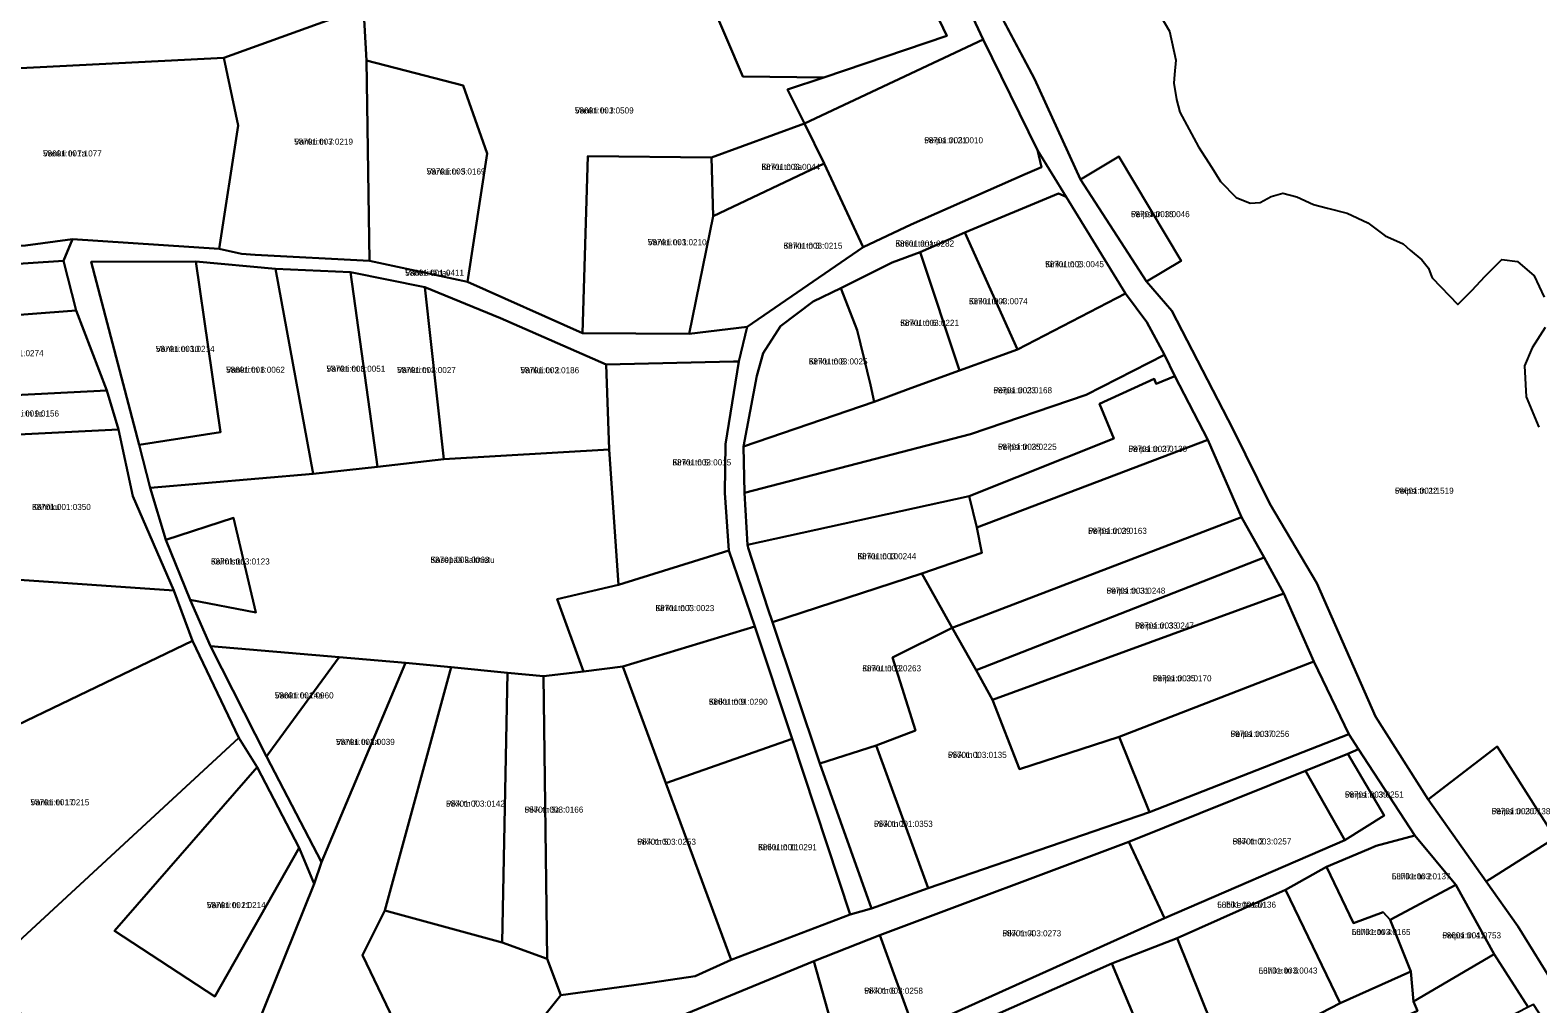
# Model space of a CAD drawing. Extents: x 663371 to 690098, y 6476568 to 6518353.
# Drawn here: x 687904.6 to 688276.7, y 6492280 to 6492520.5 of the extents above; entities that cross this region are included whole.
import ezdxf

# ---------------------------------------------------------------- set-up
doc = ezdxf.new("R2010")
doc.units = 0
for name, color, linetype in [('L_AADRESS', 7, 'Continuous'), ('PIIR', 7, 'Continuous'), ('TUNNUS', 7, 'Continuous')]:
    doc.layers.add(name, color=color, linetype=linetype)

msp = doc.modelspace()

# ---------------------------------------------------------------- linework, layer by layer
at = {"layer": 'PIIR'}
for points in [[(687919.02, 6492840.71), (687943.62, 6492789.47), (687948.89, 6492780.18), (687957.42, 6492767.74), (687964.9, 6492758.61), (687985.77, 6492739.07), (688015.25, 6492717.52), (688014.84, 6492716.95), (687998.32, 6492695.33), (688028.7, 6492662.54), (688033.9, 6492656.68), (687990.98, 6492641.02), (687973.52, 6492619.07), (687972.11, 6492556.04), (687977.61, 6492541.58), (687986.85, 6492526.07), (687952.4, 6492513.63), (687860.02, 6492508.91)], [(688278.99, 6492274.73), (688275.61, 6492279.88), (688274.32, 6492279.22), (688265.92, 6492292.28), (688256.41, 6492309.4), (688246.32, 6492321.62), (688232.41, 6492342.93), (688230, 6492346.63), (688221.38, 6492364.54), (688213.95, 6492381.34), (688209.13, 6492390.26), (688203.57, 6492400.22), (688195.24, 6492419.29), (688187.08, 6492435), (688184.54, 6492440.33), (688180.18, 6492448.35), (688174.88, 6492455.41), (688160.23, 6492479.29), (688153.21, 6492490.87), (688139.77, 6492518.16), (688125.34, 6492549.07)], [(688140.56, 6492530.91), (688152.43, 6492508.44), (688163.82, 6492483.59), (688180.1, 6492458.37), (688186.35, 6492451.18), (688201.49, 6492421.9), (688210.55, 6492403.48), (688222.14, 6492383.92), (688236.61, 6492351), (688249.61, 6492330.52), (688263.9, 6492310.29), (688271.73, 6492299.19), (688281.22, 6492283.96)], [(688281.22, 6492283.96), (688271.73, 6492299.19), (688263.9, 6492310.29), (688280.93, 6492321.06), (688266.61, 6492343.61), (688249.61, 6492330.52), (688236.61, 6492351), (688222.14, 6492383.92), (688210.55, 6492403.48), (688201.49, 6492421.9), (688186.35, 6492451.18), (688180.1, 6492458.37), (688188.68, 6492463.51), (688173.26, 6492489.24), (688163.82, 6492483.59), (688152.43, 6492508.44), (688140.62, 6492530.8)], [(688183.13, 6492524.64), (688185.79, 6492520.2), (688187.35, 6492513.05), (688187.01, 6492509.53), (688186.81, 6492507.39), (688187.51, 6492503.36), (688188.33, 6492500.18), (688192.91, 6492491.64), (688196.18, 6492486.56), (688198.32, 6492483.07), (688202.22, 6492479.12), (688205.64, 6492477.75), (688208.12, 6492477.95), (688210.85, 6492479.41), (688213.78, 6492480.23), (688217.19, 6492479.29), (688221.27, 6492477.4), (688224.73, 6492476.49), (688229.58, 6492475.25), (688234.74, 6492472.85), (688238.98, 6492469.67), (688242.52, 6492468.08), (688243.4, 6492467.69), (688245.2, 6492466.14), (688248.03, 6492463.72), (688249.69, 6492461.73), (688250.24, 6492460.17), (688250.56, 6492459.27), (688256.94, 6492452.76), (688260.49, 6492456.29), (688263.61, 6492459.64), (688267.25, 6492463.26), (688267.81, 6492463.82), (688271.63, 6492463.35), (688275.77, 6492459.84), (688278.2, 6492454.54)], [(688278.45, 6492447.06), (688275.31, 6492442.03), (688273.36, 6492437.6), (688273.79, 6492429.94), (688276.91, 6492422.4)], [(688007.94, 6492247.62), (688035.52, 6492282.19), (688055.96, 6492285.02), (688068.71, 6492286.9), (688077.56, 6492290.93), (688107, 6492302.08), (688112.22, 6492303.57), (688126.22, 6492308.65), (688180.84, 6492327.37), (688230, 6492346.63), (688232.41, 6492342.93), (688229.75, 6492341.79), (688219.35, 6492337.62), (688175.77, 6492320.04), (688114.31, 6492297.03), (688098.03, 6492290.61), (688061.06, 6492275.35)]]:
    msp.add_lwpolyline(points, dxfattribs=at)
for points in [[(687977.61, 6492541.58), (688034.88, 6492559.77), (688042.34, 6492548.11), (688047.6, 6492532.68), (688055.58, 6492534.27), (688060.58, 6492523.84), (688072.21, 6492528.37), (688080.45, 6492509), (688100.45, 6492508.81), (688091.5, 6492505.79), (688095.7, 6492497.39), (688072.78, 6492489.02), (688042.26, 6492489.34), (688040.92, 6492445.66), (688012.56, 6492458.29), (688017.36, 6492489.98), (688011.42, 6492506.84), (687987.57, 6492513.01), (687986.85, 6492526.07)], [(688139.77, 6492518.16), (688095.7, 6492497.39), (688091.5, 6492505.79), (688100.45, 6492508.81), (688130.83, 6492519.07), (688117.88, 6492546.17), (688125.34, 6492549.07)], [(688130.83, 6492519.07), (688100.45, 6492508.81), (688080.45, 6492509), (688072.21, 6492528.37), (688117.88, 6492546.17)], [(687955.96, 6492496.94), (687952.4, 6492513.63), (687986.85, 6492526.07), (687987.57, 6492513.01), (687988.32, 6492463.54), (687960.12, 6492464.96), (687956.75, 6492465.23), (687951.2, 6492466.48)], [(688139.77, 6492518.16), (688153.21, 6492490.87), (688154.16, 6492486.67), (688150.16, 6492484.89), (688122.03, 6492472.51), (688110.19, 6492466.92), (688100.56, 6492487.52), (688095.7, 6492497.39)], [(687955.96, 6492496.94), (687951.2, 6492466.48), (687915.08, 6492468.87), (687903.44, 6492467.31), (687869.52, 6492465.35), (687862.95, 6492464.93), (687861.03, 6492481.76), (687860.02, 6492508.91), (687952.4, 6492513.63)], [(687988.32, 6492463.54), (687987.57, 6492513.01), (688011.42, 6492506.84), (688017.36, 6492489.98), (688012.56, 6492458.29)], [(688100.56, 6492487.52), (688073.14, 6492474.53), (688072.78, 6492489.02), (688095.7, 6492497.39)], [(688040.92, 6492445.66), (688042.26, 6492489.34), (688072.78, 6492489.02), (688073.14, 6492474.53), (688067.23, 6492445.47)], [(688154.16, 6492486.67), (688153.21, 6492490.87), (688160.23, 6492479.29), (688158.39, 6492480.11), (688135.29, 6492470.54), (688124.28, 6492465.64), (688117.34, 6492463.1), (688104.69, 6492456.74), (688097.86, 6492453.45), (688089.77, 6492447.36), (688085.47, 6492440.7), (688083.9, 6492435.09), (688080.66, 6492417.7), (688080.89, 6492406.21), (688081.65, 6492393.37), (688081.76, 6492392.61), (688086.62, 6492377.63), (688087.76, 6492374.28), (688099.47, 6492339.4), (688112.22, 6492303.57), (688107, 6492302.08), (688092.61, 6492345.45), (688083.4, 6492373.2), (688077.02, 6492391.96), (688076.02, 6492406.19), (688076.23, 6492418.21), (688079.5, 6492438.68), (688081.51, 6492447.21), (688110.19, 6492466.92), (688122.03, 6492472.51), (688150.16, 6492484.89)], [(688073.14, 6492474.53), (688100.56, 6492487.52), (688110.19, 6492466.92), (688081.51, 6492447.21), (688067.23, 6492445.47)], [(688163.82, 6492483.59), (688173.26, 6492489.24), (688188.68, 6492463.51), (688180.1, 6492458.37)], [(688135.29, 6492470.54), (688158.39, 6492480.11), (688160.23, 6492479.29), (688174.88, 6492455.41), (688148.28, 6492441.6)], [(687856.56, 6492464.52), (687862.95, 6492464.93), (687869.52, 6492465.35), (687903.44, 6492467.31), (687915.08, 6492468.87), (687912.79, 6492463.47), (687865.33, 6492460.36), (687865.24, 6492447.41), (687868.47, 6492428.71), (687859.94, 6492432.28)], [(687912.79, 6492463.47), (687915.08, 6492468.87), (687951.2, 6492466.48), (687956.75, 6492465.23), (687960.12, 6492464.96), (687988.32, 6492463.54), (688012.56, 6492458.29), (688040.92, 6492445.66), (688067.23, 6492445.47), (688081.51, 6492447.21), (688079.5, 6492438.68), (688078.17, 6492438.67), (688046.73, 6492437.95), (688020.67, 6492449.38), (688002.03, 6492457.02), (687983.62, 6492460.68), (687965.14, 6492461.55), (687945.49, 6492463.31), (687919.63, 6492463.27), (687931.46, 6492418.1), (687934.21, 6492407.47), (687938.1, 6492394.65), (687944.11, 6492379.82), (687949.06, 6492368.35), (687962.89, 6492341.09), (687976.52, 6492315.01), (687974.65, 6492309.67), (687971.02, 6492318.59), (687960.6, 6492338.49), (687956.1, 6492345.77), (687944.65, 6492369.68), (687940.06, 6492382.09), (687929.94, 6492405.44), (687926.39, 6492421.88), (687923.55, 6492431.48), (687915.95, 6492451.22)], [(688124.28, 6492465.64), (688135.29, 6492470.54), (688148.28, 6492441.6), (688142.55, 6492439.52), (688133.96, 6492436.41)], [(687915.95, 6492451.22), (687865.24, 6492447.41), (687865.33, 6492460.36), (687912.79, 6492463.47)], [(687931.46, 6492418.1), (687919.63, 6492463.27), (687945.49, 6492463.31), (687951.58, 6492421.24)], [(687934.21, 6492407.47), (687931.46, 6492418.1), (687951.58, 6492421.24), (687945.49, 6492463.31), (687965.14, 6492461.55), (687974.43, 6492410.9)], [(688133.96, 6492436.41), (688121.93, 6492432.03), (688112.87, 6492428.72), (688111.99, 6492432.92), (688108.69, 6492446.39), (688104.69, 6492456.74), (688117.34, 6492463.1), (688124.28, 6492465.64)], [(687983.62, 6492460.68), (687990.33, 6492412.65), (687974.43, 6492410.9), (687965.14, 6492461.55)], [(688002.03, 6492457.02), (688006.69, 6492414.5), (687990.33, 6492412.65), (687983.62, 6492460.68)], [(688020.67, 6492449.38), (688046.73, 6492437.95), (688047.45, 6492416.94), (688006.69, 6492414.5), (688002.03, 6492457.02)], [(688104.69, 6492456.74), (688108.69, 6492446.39), (688111.99, 6492432.92), (688112.87, 6492428.72), (688080.66, 6492417.7), (688083.9, 6492435.09), (688085.47, 6492440.7), (688089.77, 6492447.36), (688097.86, 6492453.45)], [(688180.18, 6492448.35), (688184.54, 6492440.33), (688165.22, 6492430.41), (688136.65, 6492420.71), (688080.89, 6492406.21), (688080.66, 6492417.7), (688112.87, 6492428.72), (688121.93, 6492432.03), (688133.96, 6492436.41), (688142.55, 6492439.52), (688148.28, 6492441.6), (688174.88, 6492455.41)], [(687923.55, 6492431.48), (687868.47, 6492428.71), (687865.24, 6492447.41), (687915.95, 6492451.22)], [(688078.17, 6492438.67), (688079.5, 6492438.68), (688076.23, 6492418.21), (688076.02, 6492406.19), (688077.02, 6492391.96), (688049.79, 6492383.53), (688047.45, 6492416.94), (688046.73, 6492437.95)], [(688165.22, 6492430.41), (688184.54, 6492440.33), (688187.08, 6492435), (688182.5, 6492433.14), (688181.95, 6492434.35), (688168.53, 6492428.22), (688172.02, 6492419.63), (688136.3, 6492405.37), (688081.65, 6492393.37), (688080.89, 6492406.21), (688136.65, 6492420.71)], [(688181.95, 6492434.35), (688182.5, 6492433.14), (688187.08, 6492435), (688195.24, 6492419.29), (688138.25, 6492397.68), (688136.3, 6492405.37), (688172.02, 6492419.63), (688168.53, 6492428.22)], [(687869.85, 6492418.65), (687868.47, 6492428.71), (687923.55, 6492431.48), (687926.39, 6492421.88), (687875.39, 6492419.35)], [(687875.39, 6492419.35), (687926.39, 6492421.88), (687929.94, 6492405.44), (687940.06, 6492382.09), (687881.67, 6492386.14)], [(688139.48, 6492391.42), (688138.25, 6492397.68), (688195.24, 6492419.29), (688203.57, 6492400.22), (688132.17, 6492372.91), (688124.63, 6492386.3)], [(687934.21, 6492407.47), (687974.43, 6492410.9), (687990.33, 6492412.65), (688006.69, 6492414.5), (688047.45, 6492416.94), (688049.79, 6492383.53), (688034.67, 6492379.95), (688041.14, 6492362.07), (688031.24, 6492360.93), (688022.37, 6492361.77), (688008.51, 6492363.22), (687997.26, 6492364.25), (687980.89, 6492365.62), (687949.06, 6492368.35), (687944.11, 6492379.82), (687960.31, 6492376.68), (687954.75, 6492400.02), (687938.1, 6492394.65)], [(688081.65, 6492393.37), (688136.3, 6492405.37), (688138.25, 6492397.68), (688139.48, 6492391.42), (688124.63, 6492386.3), (688087.76, 6492374.28), (688086.62, 6492377.63), (688081.76, 6492392.61)], [(687938.1, 6492394.65), (687954.75, 6492400.02), (687960.31, 6492376.68), (687944.11, 6492379.82)], [(688132.17, 6492372.91), (688203.57, 6492400.22), (688209.13, 6492390.26), (688138.09, 6492362.42)], [(687940.06, 6492382.09), (687944.65, 6492369.68), (687869.01, 6492333.31), (687835.93, 6492389.45), (687881.67, 6492386.14)], [(688083.4, 6492373.2), (688050.89, 6492363.36), (688041.14, 6492362.07), (688034.67, 6492379.95), (688049.79, 6492383.53), (688077.02, 6492391.96)], [(688213.95, 6492381.34), (688142.05, 6492355.15), (688138.09, 6492362.42), (688209.13, 6492390.26)], [(688117.41, 6492365.59), (688123.08, 6492347.57), (688113.35, 6492343.86), (688099.47, 6492339.4), (688087.76, 6492374.28), (688124.63, 6492386.3), (688132.17, 6492372.91)], [(688221.38, 6492364.54), (688173.36, 6492345.94), (688148.79, 6492338.01), (688142.05, 6492355.15), (688213.95, 6492381.34)], [(688050.89, 6492363.36), (688083.4, 6492373.2), (688092.61, 6492345.45), (688061.49, 6492334.57)], [(688180.84, 6492327.37), (688126.22, 6492308.65), (688113.35, 6492343.86), (688123.08, 6492347.57), (688117.41, 6492365.59), (688132.17, 6492372.91), (688138.09, 6492362.42), (688142.05, 6492355.15), (688148.79, 6492338.01), (688173.36, 6492345.94)], [(687956.1, 6492345.77), (687895.03, 6492289.39), (687894.43, 6492288.82), (687894.03, 6492288.45), (687869.01, 6492333.31), (687944.65, 6492369.68)], [(687964.44, 6492343.19), (687962.89, 6492341.09), (687949.06, 6492368.35), (687980.89, 6492365.62)], [(687992.09, 6492303.09), (687986.57, 6492292.04), (688007.94, 6492247.62), (688005.84, 6492240.83), (687994.89, 6492222.84), (687977.17, 6492230.46), (687947.92, 6492243.24), (687974.65, 6492309.67), (687976.52, 6492315.01), (687997.26, 6492364.25), (688008.51, 6492363.22)], [(687976.52, 6492315.01), (687962.89, 6492341.09), (687964.44, 6492343.19), (687980.89, 6492365.62), (687997.26, 6492364.25)], [(688022.37, 6492361.77), (688021.07, 6492295.16), (687992.09, 6492303.09), (688008.51, 6492363.22)], [(688035.52, 6492282.19), (688032.16, 6492291.13), (688031.24, 6492360.93), (688041.14, 6492362.07), (688050.89, 6492363.36), (688061.49, 6492334.57), (688077.56, 6492290.93), (688068.71, 6492286.9), (688055.96, 6492285.02)], [(688173.36, 6492345.94), (688221.38, 6492364.54), (688230, 6492346.63), (688180.84, 6492327.37)], [(688021.07, 6492295.16), (688022.37, 6492361.77), (688031.24, 6492360.93), (688032.16, 6492291.13)], [(687895.03, 6492289.39), (687956.1, 6492345.77), (687960.6, 6492338.49), (687925.4, 6492298.08), (687950.14, 6492281.83), (687971.02, 6492318.59), (687974.65, 6492309.67), (687947.92, 6492243.24), (687944.94, 6492231.13), (687929.9, 6492232.35)], [(688061.49, 6492334.57), (688092.61, 6492345.45), (688107, 6492302.08), (688077.56, 6492290.93)], [(688232.41, 6492342.93), (688246.32, 6492321.62), (688236.81, 6492319.07), (688234.88, 6492318.24), (688224.53, 6492313.9), (688214.37, 6492308.19), (688187.68, 6492296.27), (688171.57, 6492290.01), (688118.51, 6492266.59), (688106.24, 6492264.66), (688095.83, 6492265.14), (688104.18, 6492268.6), (688114.71, 6492270.25), (688122.81, 6492273.41), (688184.51, 6492301.17), (688229.05, 6492320.45), (688238.77, 6492326.55), (688229.75, 6492341.79)], [(688112.22, 6492303.57), (688099.47, 6492339.4), (688113.35, 6492343.86), (688126.22, 6492308.65)], [(688229.05, 6492320.45), (688219.35, 6492337.62), (688229.75, 6492341.79), (688238.77, 6492326.55)], [(688266.61, 6492343.61), (688280.93, 6492321.06), (688263.9, 6492310.29), (688249.61, 6492330.52)], [(687925.4, 6492298.08), (687960.6, 6492338.49), (687971.02, 6492318.59), (687950.14, 6492281.83)], [(688219.35, 6492337.62), (688229.05, 6492320.45), (688184.51, 6492301.17), (688175.77, 6492320.04)], [(688175.77, 6492320.04), (688184.51, 6492301.17), (688122.81, 6492273.41), (688114.31, 6492297.03)], [(688231.15, 6492299.97), (688224.53, 6492313.9), (688234.88, 6492318.24), (688236.81, 6492319.07), (688246.32, 6492321.62), (688256.41, 6492309.4), (688240.25, 6492300.83), (688238.5, 6492302.68)], [(688214.37, 6492308.19), (688224.53, 6492313.9), (688231.15, 6492299.97), (688238.5, 6492302.68), (688240.25, 6492300.83), (688245.33, 6492288.06), (688227.86, 6492280.21)], [(688214.37, 6492308.19), (688227.86, 6492280.21), (688206.26, 6492269.01), (688196.27, 6492274.77), (688187.68, 6492296.27)], [(688240.25, 6492300.83), (688256.41, 6492309.4), (688265.92, 6492292.28), (688246.02, 6492280.66), (688245.33, 6492288.06)], [(687992.09, 6492303.09), (688021.07, 6492295.16), (688032.16, 6492291.13), (688035.52, 6492282.19), (688007.94, 6492247.62), (687986.57, 6492292.04)], [(688187.68, 6492296.27), (688196.27, 6492274.77), (688143.64, 6492250.23), (688133.88, 6492244.78), (688119.71, 6492231.98), (688063.83, 6492138.79), (688058.89, 6492147.33), (688118.33, 6492244.23), (688128.13, 6492253.4), (688154, 6492268.51), (688156.82, 6492263.95), (688177.94, 6492274.72), (688171.57, 6492290.01)], [(688098.03, 6492290.61), (688114.31, 6492297.03), (688122.81, 6492273.41), (688114.71, 6492270.25), (688104.18, 6492268.6)], [(688246.02, 6492280.66), (688265.92, 6492292.28), (688274.32, 6492279.22), (688222.97, 6492252.76), (688212.78, 6492262.68), (688246.98, 6492278.34)], [(688044.56, 6492221.61), (688061.06, 6492275.35), (688098.03, 6492290.61), (688104.18, 6492268.6), (688095.83, 6492265.14), (688083.21, 6492245.53), (688090.28, 6492240.52), (688063.09, 6492193.66), (688046.74, 6492172.12), (688041.18, 6492183.91), (688050.22, 6492197.52)], [(688052.37, 6492160.73), (688073.22, 6492185.93), (688118.51, 6492266.59), (688171.57, 6492290.01), (688177.94, 6492274.72), (688156.82, 6492263.95), (688154, 6492268.51), (688128.13, 6492253.4), (688118.33, 6492244.23), (688058.89, 6492147.33)], [(688212.78, 6492262.68), (688206.26, 6492269.01), (688227.86, 6492280.21), (688245.33, 6492288.06), (688246.02, 6492280.66), (688246.98, 6492278.34)]]:
    msp.add_lwpolyline(points, close=True, dxfattribs=at)

# ---------------------------------------------------------------- texts
at = {"layer": 'L_AADRESS'}
for s, p in [('Vankri tn 3', (688039.03, 6492499.89)), ('Vankri tn 7', (687969.76, 6492492.19)), ('Peipsi tn 21', (688125.24, 6492492.54)), ('Vankri tn 7a', (687907.76, 6492489.28)), ('Vankri tn 5', (688002.46, 6492484.82)), ('Kiriku tn 3a', (688085.06, 6492485.96)), ('Peipsi tn 18', (688176.25, 6492474.29)), ('Vankri tn 1', (688057.03, 6492467.36)), ('Kiriku tn 3', (688090.54, 6492466.49)), ('Kiriku tänav', (688118.12, 6492467.03)), ('Kiriku tn 2', (688155.09, 6492461.94)), ('Vankri tänav', (687997.15, 6492459.81)), ('Kiriku tn 4', (688136.28, 6492452.79)), ('Kiriku tn 6', (688119.32, 6492447.45)), ('Vankri tn 10', (687935.61, 6492441.02)), ('Vankri tn 8', (687952.95, 6492435.86)), ('Vankri tn 6', (687977.73, 6492436.11)), ('Vankri tn 4', (687995.15, 6492435.79)), ('Vankri tn 2', (688025.58, 6492435.76)), ('Kiriku tn 8', (688096.76, 6492437.92)), ('Peipsi tn 23', (688142.29, 6492430.81)), ('Vankri tn 9c', (687897.21, 6492425.07)), ('Peipsi tn 25', (688143.43, 6492416.85)), ('Peipsi tn 27', (688175.62, 6492416.34)), ('Kiriku tn 5', (688063.11, 6492412.99)), ('Peipsi tn 22', (688241.4, 6492406.01)), ('Kähriku', (687905.06, 6492401.99)), ('Peipsi tn 29', (688165.68, 6492396.1)), ('Kalmistu', (687949.21, 6492388.53)), ('Kasepää kalmistu', (688003.4, 6492388.94)), ('Kiriku tn 10', (688108.76, 6492389.83)), ('Peipsi tn 31', (688170.24, 6492381.32)), ('Kiriku tn 7', (688058.92, 6492377.02)), ('Peipsi tn 33', (688177.29, 6492372.71)), ('Kiriku tn 12', (688109.96, 6492362.15)), ('Peipsi tn 35', (688181.65, 6492359.68)), ('Vankri tn 14a', (687964.98, 6492355.45)), ('Kiriku tn 9', (688072.09, 6492353.88)), ('Vankri tn 14', (687980.07, 6492343.98)), ('Peipsi tn 37', (688200.84, 6492345.96)), ('Pikk tn 1', (688131.09, 6492340.78)), ('Vankri tn 17', (687904.69, 6492329.07)), ('Pikk tn 7', (688007.23, 6492328.74)), ('Peipsi tn 39', (688229.06, 6492330.98)), ('Pikk tn 5a', (688026.61, 6492327.26)), ('Peipsi tn 20', (688265.27, 6492326.87)), ('Pikk tn 3', (688112.84, 6492323.75)), ('Pikk tn 5', (688054.4, 6492319.32)), ('Kiriku tn 11', (688084.25, 6492317.99)), ('Pikk tn 2', (688201.34, 6492319.4)), ('Lühike tn 2', (688240.63, 6492310.79)), ('Vankri tn 21', (687948.21, 6492303.68)), ('Lühike tänav', (688197.55, 6492303.79)), ('Pikk tn 4', (688144.53, 6492296.73)), ('Lühike tn 4', (688230.75, 6492297.05)), ('Peipsi tn 41', (688253.09, 6492296.21)), ('Lühike tn 6', (688207.77, 6492287.52)), ('Pikk tn 6', (688110.42, 6492282.54))]:
    msp.add_text(s, height=1.5, dxfattribs=at).set_placement(p)
at = {"layer": 'TUNNUS'}
for s, p in [('58601:001:0509', (688039.03, 6492499.89)), ('58701:003:0219', (687969.76, 6492492.19)), ('58701:003:0010', (688125.24, 6492492.54)), ('58601:001:1077', (687907.76, 6492489.28)), ('58701:003:0169', (688002.46, 6492484.82)), ('58701:003:0044', (688085.06, 6492485.96)), ('58701:003:0046', (688176.25, 6492474.29)), ('58701:003:0210', (688057.03, 6492467.36)), ('58701:003:0215', (688090.54, 6492466.49)), ('58601:001:0282', (688118.12, 6492467.03)), ('58701:003:0045', (688155.09, 6492461.94)), ('58601:001:0411', (687997.15, 6492459.81)), ('58701:003:0074', (688136.28, 6492452.79)), ('58701:003:0221', (688119.32, 6492447.45)), ('58701:001:0274', (687893.4, 6492439.96)), ('58701:003:0214', (687935.61, 6492441.02)), ('58601:001:0062', (687952.95, 6492435.86)), ('58701:003:0051', (687977.73, 6492436.11)), ('58701:003:0027', (687995.15, 6492435.79)), ('58701:003:0186', (688025.58, 6492435.76)), ('58701:003:0025', (688096.76, 6492437.92)), ('58701:003:0168', (688142.29, 6492430.81)), ('58701:001:0156', (687897.21, 6492425.07)), ('58701:003:0225', (688143.43, 6492416.85)), ('58701:003:0130', (688175.62, 6492416.34)), ('58701:003:0015', (688063.11, 6492412.99)), ('58601:001:1519', (688241.4, 6492406.01)), ('58701:001:0350', (687905.06, 6492401.99)), ('58701:003:0163', (688165.68, 6492396.1)), ('58701:003:0123', (687949.21, 6492388.53)), ('58701:003:0063', (688003.4, 6492388.94)), ('58701:003:0244', (688108.76, 6492389.83)), ('58701:003:0248', (688170.24, 6492381.32)), ('58701:003:0023', (688058.92, 6492377.02)), ('58701:003:0247', (688177.29, 6492372.71)), ('58701:003:0263', (688109.96, 6492362.15)), ('58701:003:0170', (688181.65, 6492359.68)), ('58601:001:0960', (687964.98, 6492355.45)), ('58601:001:0290', (688072.09, 6492353.88)), ('58701:003:0039', (687980.07, 6492343.98)), ('58701:003:0256', (688200.84, 6492345.96)), ('58701:003:0135', (688131.09, 6492340.78)), ('58701:001:0215', (687904.69, 6492329.07)), ('58701:003:0142', (688007.23, 6492328.74)), ('58701:003:0251', (688229.06, 6492330.98)), ('58701:003:0166', (688026.61, 6492327.26)), ('58701:003:0138', (688265.27, 6492326.87)), ('58701:001:0353', (688112.84, 6492323.75)), ('58701:003:0253', (688054.4, 6492319.32)), ('58601:001:0291', (688084.25, 6492317.99)), ('58701:003:0257', (688201.34, 6492319.4)), ('58701:003:0137', (688240.63, 6492310.79)), ('58701:001:0214', (687948.21, 6492303.68)), ('58601:001:0136', (688197.55, 6492303.79)), ('58701:003:0273', (688144.53, 6492296.73)), ('58701:003:0165', (688230.75, 6492297.05)), ('58601:001:0753', (688253.09, 6492296.21)), ('58701:003:0043', (688207.77, 6492287.52)), ('58701:003:0258', (688110.42, 6492282.54))]:
    msp.add_text(s, height=1.5, dxfattribs=at).set_placement(p)

doc.saveas('drawing.dxf')
